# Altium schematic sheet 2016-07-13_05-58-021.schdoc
size 361 x 127 mm; SheetNumber: 1; SheetTotal: 1
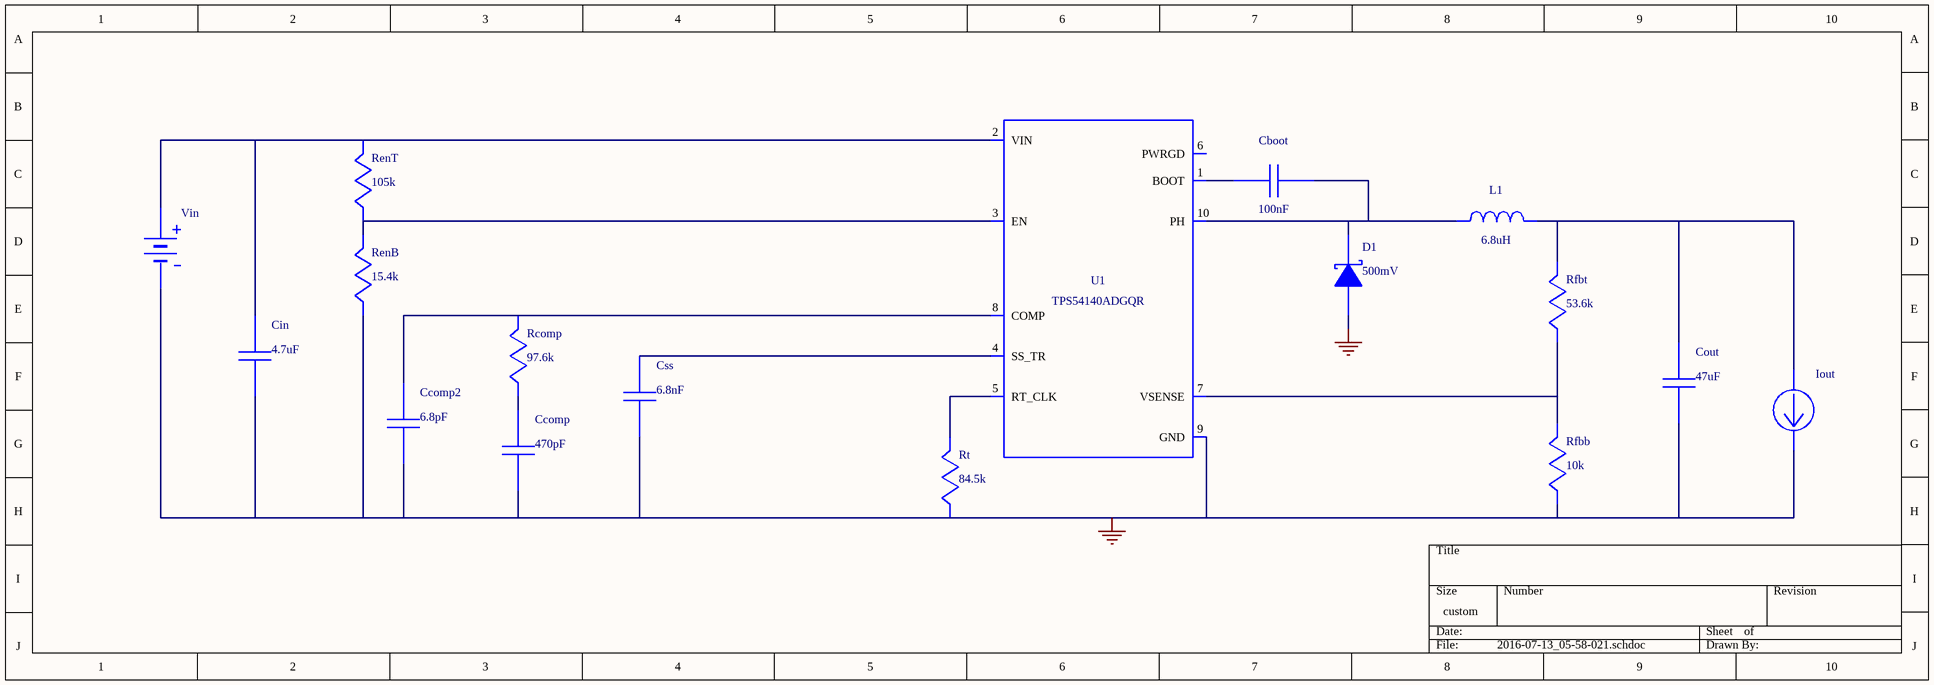
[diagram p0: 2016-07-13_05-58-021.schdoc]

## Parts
Cboot  value 100nF  (hidden comment: GRM155R61A104KA01D)
Ccomp  value 470pF  (hidden comment: CC0805KRX7R9BB471)
Ccomp2  value 6.8pF  (hidden comment: GRM1555C1H6R8CA01D)
Cin  value 4.7uF  (hidden comment: GRM21BC81E475KA12L)
Cout  value 47uF  (hidden comment: GRM31CR61A476KE15L)
Css  value 6.8nF  (hidden comment: CC0805KRX7R9BB682)
D1  value 500mV  (hidden comment: B230A-13-F)
Iout  WB_CURRENT_LOAD  (value not drawn)
L1  value 6.8uH  (hidden comment: SRN6045-6R8Y)
Rcomp  value 97.6k  (hidden comment: CRCW040297K6FKED)
RenB  value 15.4k  (hidden comment: CRCW040215K4FKED)
RenT  value 105k  (hidden comment: CRCW0402105KFKED)
Rfbb  value 10k  (hidden comment: CRCW040210K0FKED)
Rfbt  value 53.6k  (hidden comment: CRCW040253K6FKED)
Rt  value 84.5k  (hidden comment: CRCW040284K5FKED)
U1  TPS54140DGQR  (value not drawn)
Vin  WB_BATTERY  (value not drawn)

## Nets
0: Ccomp.2 Ccomp2.2 Cin.2 Cout.2 Css.2 D1.2(A) Iout.2(-) RenB.2 Rfbb.2 Rt.2 U1.9(GND) U1.11(EPAD) Vin.2(-)
NetCboot_1: Cboot.1 U1.1(BOOT)
NetCboot_2: Cboot.2 D1.1(K) L1.2 U1.10(PH)
NetCcomp2_1: Ccomp2.1 Rcomp.1 U1.8(COMP)
NetCcomp_1: Ccomp.1 Rcomp.2
NetCin_1: Cin.1 RenT.1 U1.2(VIN) Vin.1(+)
NetCout_1: Cout.1 Iout.1(+) L1.1 Rfbt.1
NetCss_1: Css.1 U1.4(SS_TR)
NetRenB_1: RenB.1 RenT.2 U1.3(EN)
NetRfbb_1: Rfbb.1 Rfbt.2 U1.7(VSENSE)
NetRt_1: Rt.1 U1.5(RT_CLK)

Not connected (* = marked no-connect by the designer): U1 6(PWRGD)

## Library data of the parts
Cboot = GRM155R61A104KA01D: GRM155R61A104KA0; Manufacturer Name: MuRata
Ccomp = CC0805KRX7R9BB471: CC0805KRX7R9BB47; Manufacturer Name: Yageo America
Ccomp2 = GRM1555C1H6R8CA01D: GRM1555C1H6R8CA0; Manufacturer Name: MuRata
Cin = GRM21BC81E475KA12L: GRM21BC81E475KA1; Manufacturer Name: MuRata
Cout = GRM31CR61A476KE15L: GRM31CR61A476KE1; Manufacturer Name: MuRata
Css = CC0805KRX7R9BB682: CC0805KRX7R9BB68; Manufacturer Name: Yageo America
D1 = B230A-13-F: Manufacturer Name: Diodes Inc.
L1 = SRN6045-6R8Y: Manufacturer Name: Bourns
Rcomp = CRCW040297K6FKED: Manufacturer Name: Vishay-Dale
RenB = CRCW040215K4FKED: Manufacturer Name: Vishay-Dale
RenT = CRCW0402105KFKED: Manufacturer Name: Vishay-Dale
Rfbb = CRCW040210K0FKED: Manufacturer Name: Vishay-Dale
Rfbt = CRCW040253K6FKED: Manufacturer Name: Vishay-Dale
Rt = CRCW040284K5FKED: Manufacturer Name: Vishay-Dale
U1 = TPS54140DGQR: TPS54140ADGQR; Manufacturer Name: Texas Instruments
